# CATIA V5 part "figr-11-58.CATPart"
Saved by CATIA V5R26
Part number: Part1
Bounding box of the stored display mesh (mm): x -59.829 to 59.829, y -71.429 to 72.174, z -61 to 76
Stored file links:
  D:\_Deepak\CATIA\CATIA V5-6R2016_Deepak\Resources\Part files\Partfiles\c11_catia_v5_6r2016_prt\figr-11-58.CATPart
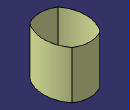
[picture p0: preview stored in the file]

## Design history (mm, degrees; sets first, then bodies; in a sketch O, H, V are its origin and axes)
Set1
  Extrude1: Element1 Sketch1, Lim1 76, Lim2 61, Direction xy-plane
Body1 (main body)
  Sketch1 on xy-plane, origin (0, 0, 0), H (0, 1, 0), V (-1, 0, 0)
    arc A1 centre (0, -40) radius 100 from (-60, 40) to (60, 40) cw
    point P2 (0, 60)
    point P3 (-60, 40)
    point P4 (60, 40)
    axis line L1 (-90, 0) -> (80, 0)
    point P6 (80, 0)
    point P7 (60, -40)
    point P8 (-60, -40)
    arc A2 centre (0, 40) radius 100 from (-60, -40) to (60, -40) ccw
    arc A3 centre (4.2857, 0) radius 75.7143 from (-60, 40) to (-60, -40) ccw
    arc A4 centre (0.3727, 0) radius 71.8012 from (60, -40) to (60, 40) ccw
    coincidence: A1 P2, P2 V, A3 P6
    horizontal: L1 H
    symmetry: P4 P7 L1, P3 P8 L1, A1 A2 L1
    tangency: A4 A3
  Sketch2 on xy-plane, origin (0, 0, 0), H (1, 0, 0), V (0, 1, 0)
    spline S1 through (80, 90) (60, 60) (70, 0) (50, -50) (50, -80)
    point P1 (70, 0)
    coincidence: P1 H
